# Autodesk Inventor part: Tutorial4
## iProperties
Created: 2001-11
Part Number: Tutorial4
Document SubType Name: Modeling
Designer: Renu Muthoo
Control State: 0
Master: False
Checked Out: False
Shininess: 77.0
Length Units: 11269
Angle Units: 11279
Time Units: 11290
Mass Units: 11283
Length Display Precision: 3
Angle Display Precision: 2
Density: 0.0
Volumn: 0.0
Area: 0.0
PropertySet Name: Model Information
Author: Renu Muthoo
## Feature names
1. Extrusion1
2. Extrusion2
3. Extrusion3
4. Extrusion4
5. Extrusion5
6. Extrusion6
